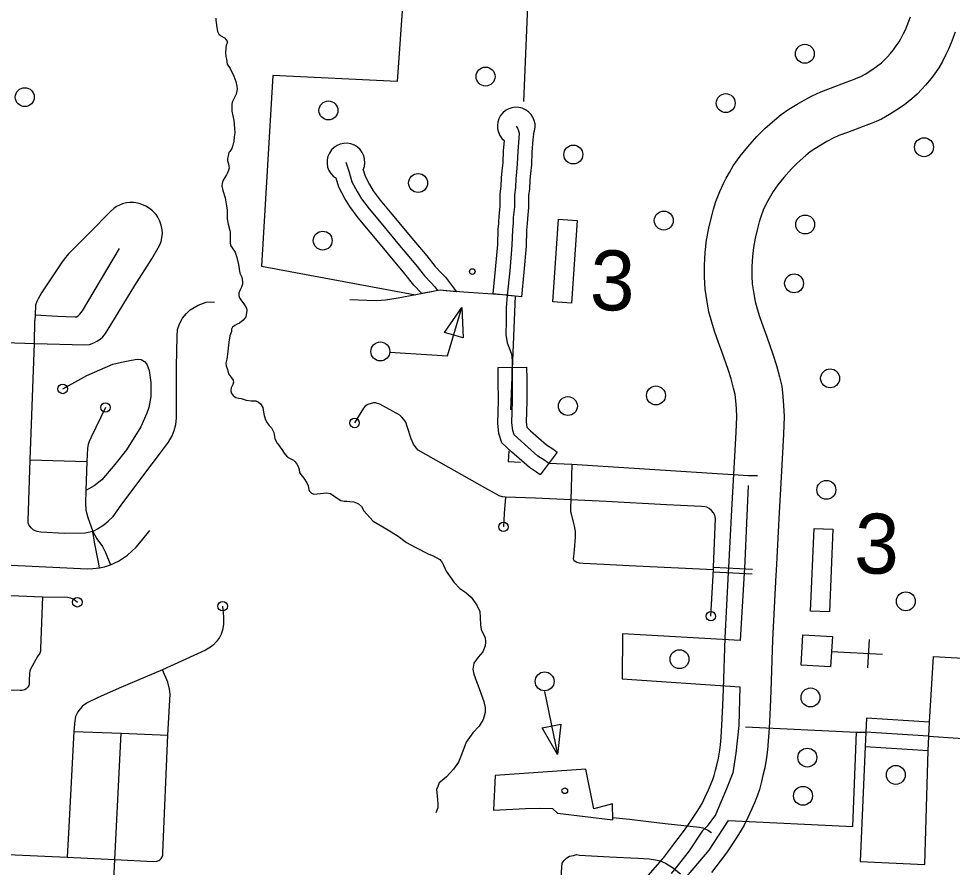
# Model space of a CAD drawing. Extents: x 653372 to 905732, y 627442 to 787275.
# Drawn here: x 671338 to 676272, y 753633 to 758117 of the extents above; entities that cross this region are included whole.
import ezdxf

# ---------------------------------------------------------------- set-up
doc = ezdxf.new("R2010")
doc.units = 0
for name, color, linetype in [('10', 7, 'Continuous'), ('31', 7, 'Continuous'), ('33', 7, 'Continuous'), ('34', 7, 'Continuous'), ('35', 7, 'Continuous'), ('5', 7, 'Continuous'), ('56', 7, 'Continuous'), ('57', 7, 'Continuous'), ('6', 7, 'Continuous')]:
    doc.layers.add(name, color=color, linetype=linetype)

msp = doc.modelspace()

# ---------------------------------------------------------------- linework, layer by layer
at = {"layer": '10'}
for points in [[(674976.3, 756621.1), (674964.7, 756688.7), (674961.6, 756752.6), (674962.4, 756815.5), (674966, 756881.7), (674973.3, 756946.2), (674985.7, 757009.6), (674999.1, 757068.1), (675009.8, 757109.9), (675022.3, 757151.7), (675042.5, 757204.3), (675061.9, 757245.4), (675076.8, 757274.8), (675094.1, 757304.6), (675114.4, 757339.7), (675150.9, 757390.5), (675190.5, 757439.6), (675239.2, 757494.6), (675281.2, 757536.8), (675334.4, 757582.9), (675367.1, 757611), (675407.5, 757639.5), (675451.5, 757666), (675488.5, 757686.5), (675530.8, 757709.8), (675576.2, 757729.9), (675627.9, 757750.1), (675711.1, 757781), (675749.8, 757796.3), (675774.4, 757806.2), (675787.8, 757811.7), (675810.8, 757824.8), (675840.4, 757843.5), (675870.3, 757864.1), (675896.5, 757884.5), (675911.3, 757897.9), (675928.5, 757916), (675942.6, 757931.2), (675960.5, 757952.7), (675975.6, 757974.3), (675990.8, 757994.8), (675999.7, 758010.4), (676014.4, 758039), (676023.8, 758058.2), (676033.4, 758081.6), (676050.9, 758127.4)], [(676287.1, 758045.1), (676265.8, 757989.2), (676251.9, 757955.6), (676238, 757927.1), (676219.6, 757891.3), (676200.5, 757857.9), (676178.4, 757828.1), (676159.3, 757800.8), (676130.3, 757766), (676110.6, 757744.8), (676086, 757718.9), (676057.6, 757693.1), (676018.3, 757662.5), (675978.2, 757634.8), (675939.5, 757610.4), (675897.5, 757586.5), (675868.4, 757574.6), (675842.5, 757564.1), (675800.7, 757547.6), (675716.9, 757516.5), (675672.4, 757499.1), (675642, 757485.6), (675609.2, 757467.5), (675576.5, 757449.5), (675544.3, 757430), (675521, 757413.6), (675497.8, 757393.6), (675451.8, 757353.8), (675421.5, 757323.4), (675381.5, 757278.2), (675349.9, 757238.9), (675324.6, 757203.9), (675310.4, 757179.2), (675296.5, 757155.4), (675286.6, 757135.7), (675272.6, 757106.1), (675259.1, 757070.9), (675250.8, 757043.1), (675242.1, 757009.2), (675230.3, 756957.8), (675220.6, 756908), (675215.2, 756860.7), (675212.3, 756807.2), (675211.7, 756757.1), (675213.7, 756716), (675222.7, 756663.4)], [(675222.8, 756663.1), (675229.6, 756622.3), (675240.6, 756583.5), (675252.7, 756544.2), (675272.3, 756488.6), (675288.9, 756441.7), (675323.3, 756345), (675343.2, 756284), (675358.2, 756224.8), (675369.9, 756175.9), (675376.7, 756121.6), (675380, 756072.4), (675383.1, 756014.3), (675379.3, 755921), (675366.5, 755693.9), (675355.8, 755508.4), (675340.9, 755202.2), (675339.2, 755175.9), (675321.9, 754835.4), (675312.5, 754565.9), (675309, 754477.9), (675304, 754368.3), (675298.9, 754300.3), (675295.2, 754253.8), (675289.9, 754213.4), (675280.1, 754159.3), (675270.8, 754118.9), (675263.7, 754085.7), (675252.1, 754044.6), (675240, 754009.4), (675225.7, 753973.9), (675212.8, 753942.2), (675191.2, 753896.3), (675171.3, 753856.1), (675150.4, 753820.1), (675129.8, 753786.4), (675102.1, 753746.3), (675078.1, 753710.1), (675044.9, 753665.4), (674999.1, 753605.1)], [(674666.9, 753592.2), (674725.5, 753661.1), (674742.9, 753681.8), (674746.7, 753685.7), (674799.8, 753756), (674845, 753815.5), (674873.4, 753853.8), (674895.1, 753886.5), (674920.2, 753922.8), (674935.6, 753948), (674950.9, 753974.3), (674966.1, 754005), (674983.8, 754042.7), (674994, 754067.8), (675005.6, 754096.6), (675013.3, 754119), (675020.9, 754145.9), (675026.7, 754173.2), (675035.2, 754209.7), (675042.8, 754251.9), (675046.5, 754279.9), (675049.6, 754319.6), (675054.4, 754383.5), (675059.3, 754488.6), (675062.7, 754575.2), (675072.1, 754846.1), (675089.6, 755190.5), (675091.3, 755216.5), (675106.2, 755521.7), (675116.9, 755708.2), (675129.6, 755933.1), (675132.8, 756012.6), (675130.4, 756057.5), (675127.8, 756097.7), (675123.6, 756131.1), (675115.4, 756165), (675102.9, 756214.5), (675086.7, 756264.3), (675053.2, 756358.2), (675036.6, 756405.3), (675015.2, 756465.8), (675000.8, 756512.9), (674985.4, 756567.4), (674976.3, 756621.4)]]:
    msp.add_lwpolyline(points, dxfattribs=at)
at = {"layer": '31'}
for p, q in [((673291.9, 756872.5), (673291.9, 756872.5)), ((674022.4, 756208.1), (674022.4, 756208.1)), ((674183.8, 755827.2), (674093.8, 755707.2))]:
    msp.add_line(p, q, dxfattribs=at)
for points in [[(673967.4, 757549), (673974, 757538.7), (673979.9, 757523.7), (673983.3, 757511.9), (673980.9, 757485.4), (673975.7, 757416.6), (673972.6, 757349.8), (673968.1, 757306.2), (673964.9, 757270.7), (673962.5, 757224.6), (673957.6, 757187), (673957.3, 757123.3), (673951.9, 757067.2), (673950.5, 757039.1), (673947.3, 757002), (673944.3, 756919.7), (673932.8, 756785.1), (673920.2, 756655.4)], [(674058.2, 757507), (674055.7, 757479.2), (674050.5, 757412), (674047.4, 757344.2), (674042.7, 757299), (674039.7, 757265.3), (674037.2, 757217.8), (674032.6, 757182), (674032.3, 757119.5), (674026.7, 757061.8), (674025.4, 757034), (674024.1, 757019.5)], [(673874.7, 757032.6), (673875.7, 757044.2), (673877.1, 757072.6), (673882.3, 757127.1), (673882.6, 757192), (673887.7, 757231.4), (673890.1, 757276), (673893.4, 757313.4), (673897.8, 757355.3), (673900.8, 757421.2), (673904.6, 757471.2)], [(673067.2, 757359.1), (673083.7, 757306.4), (673099.2, 757255.8), (673126.7, 757203.8), (673149.6, 757166), (673190.1, 757111.6), (673253.1, 757036.4), (673342.2, 756929.4), (673436.1, 756816.2), (673483.1, 756757.6), (673517.5, 756721.6), (673535.7, 756702.5), (673551.8, 756681.5)], [(673158.5, 757318.3), (673168.8, 757284.6), (673192, 757240.8), (673211.9, 757207.9), (673249, 757158.1), (673310.7, 757084.5), (673399.8, 756977.3), (673407.4, 756968.3)], [(673291.9, 756872.5), (673284.5, 756881.5), (673195.5, 756988.4), (673131.3, 757065.1), (673087.4, 757124), (673061.4, 757166.8), (673029.6, 757227), (673015.3, 757273.6)], [(673994.9, 756648.1), (673845.6, 756662.6), (673858.1, 756791.9), (673869.4, 756924.2), (673872.4, 757006.6), (673874.7, 757032.6)], [(674024.1, 757019.5), (674022.2, 756997.4), (674019.2, 756915.1), (674007.5, 756778.3), (673994.9, 756648.1)], [(673407.4, 756968.3), (673494.2, 756863.6), (673539.6, 756807.1), (673571.8, 756773.3), (673592.8, 756751.3), (673651.5, 756674.6), (673565.8, 756681.8), (673468.3, 756664.5)], [(673468.3, 756664.5), (673426.6, 756708.2), (673378, 756768.8), (673291.9, 756872.5)], [(673872.4, 756207.2), (673872.4, 756212), (673871.6, 756273.3), (674021.6, 756275.3)], [(674138.8, 755767.2), (674117.5, 755783.1), (674082.2, 755806.4), (673993, 755884), (673956.6, 755918.4), (673948.9, 755940.8), (673944.6, 755982.5), (673948.1, 756097.6), (673947.4, 756212.7), (673946.6, 756274.3)], [(674021.6, 756275.3), (674022.4, 756213.5), (674022.4, 756208.1)], [(674093.8, 755707.2), (674074.4, 755721.8), (674036.8, 755746.5), (673942.6, 755828.4), (673891.6, 755876.6), (673875.2, 755924.7), (673869.5, 755979.8), (673873.1, 756098.5), (673872.4, 756207.2)], [(674022.4, 756208.1), (674023.1, 756096.7), (674019.8, 755985.3), (674022.4, 755959.4), (674043.4, 755939.6), (674127.6, 755866.3), (674160.7, 755844.5), (674183.8, 755827.2)], [(676150.9, 754400.8), (675818.5, 754421.4), (675811.9, 754271.5)], [(676150.9, 754400.8), (675818.5, 754421.4), (675811.9, 754271.5)], [(675811.9, 754271.5), (676144, 754251), (676150.9, 754400.8)], [(676146.3, 754326), (675815.2, 754346.4)]]:
    msp.add_lwpolyline(points, dxfattribs=at)
for centre, start, end in [((673967.4, 757549), 335.1349, 231.0844), ((673067.2, 757359.1), 335.9073, 238.725)]:
    msp.add_arc(centre, 100, start, end, dxfattribs=at)
at = {"layer": '33'}
for points in [[(671267.5, 756405.4), (671421.3, 756401.1), (671688.5, 756393.3), (671711.7, 756396), (671734.7, 756404.2), (671754.2, 756414.5), (671769.3, 756424.4), (671783.5, 756436.8), (671797.5, 756453.2), (671825.1, 756499.2), (671951.2, 756707.2), (672041.8, 756848.1), (672075.1, 756905.8), (672083.5, 756921.8), (672090.4, 756940.4), (672094.4, 756959), (672097.6, 756981.6), (672096.7, 757000.7), (672090.5, 757026.5), (672083.3, 757047.5), (672074, 757068.5), (672065.1, 757082.6), (672045.9, 757101.4), (672030, 757113.7), (672009.7, 757126.7), (671989.2, 757135.7), (671974.1, 757141.1), (671957.4, 757144.5), (671944.1, 757145.4), (671925.9, 757146), (671908.1, 757144), (671886.7, 757138.3), (671871.2, 757132.3), (671854.7, 757123.9), (671840.5, 757113.5), (671822.8, 757097.7), (671715.4, 756988.9), (671651, 756923.2), (671602.2, 756873.9), (671579.2, 756846.9), (671563.8, 756827.6), (671526, 756768.3), (671458.9, 756668.7), (671440.7, 756637.1), (671433.3, 756622.6), (671427.8, 756604), (671425.4, 756553), (671424, 756523.1)], [(673920.2, 756655.4), (673715.6, 756670.1), (673594.4, 756678.5), (673565.8, 756681.8), (673551.8, 756681.5), (673544.5, 756680), (673528.1, 756675.8), (673436.4, 756658.5), (673343, 756639.9), (673276.5, 756629), (673253.1, 756627.3), (673227.9, 756626.2), (673177.6, 756627.2), (673088.2, 756631.8)], [(673920.2, 756655.4), (673914.3, 756589.6), (673913.6, 756518.9), (673912.9, 756448.2), (673919.9, 756405), (673930.2, 756378.3), (673943, 756344.6), (673946.2, 756311.3), (673946.6, 756274.3)], [(671729.8, 755408.2), (671755.4, 755421.3), (671788.1, 755443), (671811.4, 755461.6), (671837.3, 755486.4), (671879.5, 755545.9), (671998.8, 755707.1), (672087.7, 755823.1), (672129.8, 755879.1), (672148.6, 755913.5), (672160.3, 755941.8), (672168.2, 755973.7), (672171.6, 756005.6), (672172.6, 756107.5), (672172.8, 756279.2), (672175.6, 756438.1), (672177.2, 756474.1), (672187.5, 756503.9), (672204.2, 756535.5), (672224.7, 756559.5), (672244.5, 756578.7), (672286, 756604.1), (672328.4, 756619.1), (672352.6, 756621.3), (672373.3, 756619.2)], [(671729.8, 755408.2), (671689.1, 755398.1), (671580, 755397.4), (671455.9, 755404.1), (671435.7, 755407.2), (671424.5, 755411), (671414.3, 755416.7), (671403.3, 755426.4), (671396.6, 755436), (671392.4, 755443.5), (671388.7, 755452.1), (671387.7, 755463.9), (671399.4, 755785.9), (671421.3, 756401.1), (671424, 756523.1)], [(671796.4, 756062.7), (671720.6, 755906), (671711.1, 755883.6), (671705.1, 755866.5), (671701.1, 755847.9), (671698.6, 755777), (671692.6, 755623.5), (671691.9, 755556.9), (671692.8, 755520.8), (671704.4, 755481), (671729.8, 755408.2)], [(675009.6, 755207), (675010.2, 755219.8), (675019.5, 755476.3), (675016, 755493.4), (675009.1, 755506.6), (674999.8, 755517.6), (674987.5, 755528.7), (674974.3, 755536), (674963, 755538.6), (674945.5, 755540.2), (674760.7, 755549.2), (674441.6, 755565.6), (674255.8, 755574), (674069.8, 755583.5), (673910.1, 755588.3), (673894.8, 755590.5), (673876.3, 755596.7), (673851.8, 755609.9), (673801.7, 755639.1), (673448.7, 755836.7), (673437.8, 755849.4), (673424.2, 755869.1), (673412.6, 755897.2), (673392.3, 755957.3), (673383, 755985.3), (673372.6, 755999.8), (673363.4, 756011.9), (673352.4, 756022.4), (673246.7, 756079.9), (673224.3, 756087.4), (673212.4, 756087.2), (673182.2, 756078.5), (673169.4, 756070.4), (673159.5, 756059.9), (673113, 755980.9)], [(671399.4, 755785.9), (671698.6, 755777)], [(675241.7, 755701.1), (675194.8, 755702.3), (674590.6, 755741.2), (674260.3, 755761.5), (674138.8, 755767.2)], [(674260.3, 755761.5), (674255.8, 755574), (674253.9, 755534), (674254.4, 755513.6), (674256.8, 755501), (674270.6, 755450), (674275.6, 755429.5), (674277.8, 755405.6), (674278.1, 755377.9), (674273.8, 755310.6), (674269.3, 755275), (674268.4, 755263.7), (674272.1, 755256.3), (674278.2, 755251), (674287.7, 755245.6), (674299.4, 755241.9), (674320.4, 755240.7), (674430.6, 755234.5), (674564.6, 755227.7), (675009.6, 755206.9)], [(673910.1, 755588.3), (673903.6, 755503), (673899.8, 755431.7)], [(671224.2, 755233.5), (671701.3, 755210.2), (671730.3, 755211.8), (671764.4, 755216.4), (671791.3, 755221.6), (671822.5, 755231.3), (671865.2, 755250.7), (671913.6, 755281.8), (671959.3, 755324.9), (671987.9, 755357.6), (672031.1, 755413.5)], [(671764.4, 755216.4), (671760.5, 755244.9), (671753.2, 755281.2), (671738, 755350.3), (671729.8, 755408.2), (671751.4, 755369.6), (671780.7, 755327.8), (671797, 755295.7), (671822.5, 755231.3)], [(674995.9, 754959.9), (675009.6, 755207)], [(675009, 755193.7), (675214.4, 755183.2)], [(675010.2, 755219.8), (675216.1, 755209.3)], [(671463.7, 755062.5), (671454.1, 754789.3), (671453.7, 754775.7), (671449.4, 754764.6), (671438.4, 754746.6), (671400.9, 754680.5), (671397, 754670.3), (671394.6, 754658.7), (671393.4, 754619.2), (671393.1, 754602.2), (671391.3, 754594.6), (671386.2, 754585.2), (671378.4, 754577), (671370.6, 754571.7), (671363.4, 754569.1), (671354.1, 754567.4), (671346.1, 754566.8), (671192.5, 754573)], [(671211.8, 755072), (671463.7, 755062.5), (671596.1, 755059.7), (671612.4, 755057.2), (671623.9, 755052.5), (671636, 755044.9), (671648.1, 755033.4)], [(672416, 755012.8), (672420.8, 754956.6), (672419.6, 754915.7), (672415.5, 754886.2), (672408.4, 754864.9), (672398.7, 754846.8), (672383, 754825.8), (672366.8, 754809), (672352.4, 754796), (672326.1, 754781.1), (672097.2, 754675.9), (671868.7, 754579.7), (671755.1, 754528.7), (671704.3, 754503.3), (671683.5, 754491), (671673.5, 754482.1), (671662.9, 754471.1), (671650.1, 754454.6), (671637.5, 754429.7), (671634.1, 754409.3), (671629.8, 754351.2), (671603.3, 753846.7), (671594, 753687.2)], [(671845.8, 753673.7), (672049, 753663.8), (672067.9, 753665.4), (672078.7, 753668.3), (672084.8, 753673), (672091.5, 753680.3), (672096.6, 753689.3), (672099.5, 753696.8), (672100.5, 753711.3), (672126.8, 754331.4), (672138.6, 754548), (672135.6, 754575), (672125.4, 754612), (672097.2, 754675.9)], [(671629.8, 754351.2), (671879.9, 754341.5), (672126.8, 754331.4)], [(671832.9, 753385.8), (671845.8, 753673.7), (671879.9, 754341.5)], [(675179.2, 754375.9), (675765.3, 754346.7), (675815.2, 754346.4)], [(676146.3, 754326), (676302.1, 754314.7), (676400.2, 754308.6), (676470.9, 754301.1)], [(674478.1, 753896.6), (674566.6, 753887.2), (674652.5, 753877.1), (674754, 753865), (674935.6, 753845.3), (674953.1, 753842), (674962.9, 753838.3), (674979.2, 753829.3), (674998.6, 753816.4)], [(671161.8, 753705.6), (671594, 753687.2), (671845.8, 753673.7)], [(674183.2, 753167.3), (674180.7, 753197.8), (674184.6, 753261.1), (674195, 753428.1), (674207.4, 753636.2), (674210.6, 753655), (674220.5, 753668.9), (674235.1, 753682.6), (674249.5, 753692.3), (674269.2, 753696.4), (674285.5, 753700), (674300.9, 753697.5), (674460.5, 753688.7), (674609.4, 753682.2), (674669.6, 753677.7), (674702.6, 753673.3), (674727.3, 753666.5), (674756.6, 753654.8), (674793.1, 753632.8), (674835.7, 753598)]]:
    msp.add_lwpolyline(points, dxfattribs=at)
for centre in [(671796.4, 756062.7), (673113, 755980.9), (673899.8, 755431.7), (671648.1, 755033.4), (672416, 755012.8), (674995.9, 754959.9)]:
    msp.add_circle(centre, 25, dxfattribs=at)
at = {"layer": '34'}
for points in [[(671425.4, 756553), (671543, 756546.1), (671634, 756541.2), (671644.4, 756541.6), (671652.8, 756547.3), (671661.1, 756555.2), (671675.1, 756574), (671871.7, 756903.3)], [(671570.6, 756160.6), (671698, 756231.8), (671835, 756290.9), (671880.7, 756302.4), (671933.4, 756313.6), (671964.1, 756318.6), (671985.7, 756316), (672003.2, 756306.6), (672015.6, 756292.4), (672027.4, 756258.5), (672036.4, 756195), (672037.1, 756121), (672025.5, 756063.1), (672015.7, 756032.8), (671983.9, 755960.7), (671908.2, 755838.2), (671845.7, 755762.1), (671777.2, 755681.2), (671737.8, 755648.8), (671692.6, 755623.5)]]:
    msp.add_lwpolyline(points, dxfattribs=at)
msp.add_circle((671570.6, 756160.6), 25, dxfattribs=at)
at = {"layer": '35'}
for points in [[(672379.5, 758119.3), (672379.5, 758107), (672382.1, 758096.5), (672385.5, 758070.8), (672388.9, 758049), (672395.3, 758036.1), (672402.9, 758029.9), (672406.9, 758025.7), (672424.9, 758016.2), (672433.9, 758005.5), (672438.9, 757997.9), (672439.4, 757987.8), (672434.6, 757977.8), (672433.3, 757961.8), (672430.8, 757938), (672432.8, 757918.1), (672435.7, 757902.6), (672440.5, 757877), (672455.1, 757853.8), (672474.8, 757813.6), (672486.3, 757784.5), (672490, 757760.9), (672492.6, 757746.6), (672491.1, 757735.3), (672487.6, 757717.5), (672474.9, 757694), (672466.6, 757675.5), (672464.7, 757662.9), (672465, 757649.8), (672465.1, 757628.7), (672474.5, 757579.2), (672479.2, 757537.9), (672481.1, 757513.2), (672476.3, 757492.1), (672475, 757470.5), (672469.8, 757449), (672464.1, 757432), (672453.2, 757415.9), (672449.3, 757410.5), (672444.2, 757392), (672441.9, 757377.9), (672441.6, 757366.7), (672446.7, 757349.7), (672449, 757338.5), (672449.7, 757327.2), (672446.5, 757317.3), (672442.3, 757303.2), (672436.4, 757291.7), (672418.7, 757263.5), (672413.4, 757247.2), (672411.9, 757233.8), (672417.5, 757209.7), (672428.6, 757169.8), (672435.9, 757127.4), (672440.1, 757104.5), (672439.9, 757084.7), (672439.5, 757059.6), (672445, 757032.1), (672454, 756997.1), (672455, 756991.7)], [(672455, 756991.7), (672455.8, 756935.1), (672457.4, 756919.5), (672466.4, 756906.7), (672481.8, 756883.9), (672491.4, 756856.1), (672499.1, 756817.4), (672506.6, 756773), (672516.8, 756751.5), (672520.2, 756726.9), (672520.4, 756713.9), (672515.7, 756698.5), (672505.9, 756680.6), (672501.3, 756667.2), (672500.9, 756655.3), (672504.2, 756641.7), (672516.2, 756626.2), (672528.2, 756611.3), (672534.6, 756600.2), (672541.5, 756587.5), (672543.2, 756575.5), (672540.4, 756551.5), (672538, 756540.1), (672533.7, 756534), (672525.1, 756524.4), (672504.3, 756507.9), (672492.7, 756503.6), (672479.6, 756496.7), (672468.4, 756487.7), (672461.8, 756475.9), (672462, 756464.5), (672454, 756441.8), (672448.3, 756407.2), (672442.3, 756345), (672438.3, 756317.6), (672432.5, 756297), (672434.7, 756283.4), (672440.8, 756262.9), (672447.5, 756240.9), (672461.9, 756220.2), (672470.9, 756208), (672472.6, 756197), (672470.2, 756184.1), (672460.3, 756166.2), (672458.8, 756152.7), (672461, 756139.7), (672471.5, 756125.9), (672486.3, 756116.1), (672501.8, 756111.4), (672514.2, 756111.1)], [(672514.2, 756111.1), (672540.8, 756100.7), (672566.7, 756098.3), (672592.1, 756097.5), (672604.9, 756091.4), (672616, 756081.8), (672628.5, 756062.7), (672631.4, 756038.7), (672635.5, 756019.9), (672642.1, 755997.8), (672650.4, 755981.5), (672662, 755967.1), (672674.6, 755955.8), (672686.3, 755930), (672692.1, 755898.3), (672702.9, 755876.2), (672707.9, 755870.3), (672729.3, 755840.5), (672740.7, 755821.5), (672756.8, 755802.3), (672773.1, 755792.5), (672790.5, 755784.1), (672797.6, 755777.2), (672806.1, 755766), (672815, 755751.2), (672820.2, 755734.9), (672822.8, 755718.7), (672828.8, 755708.7), (672844.5, 755688.7), (672861.4, 755665.3), (672868.2, 755648.5), (672871.3, 755630.2), (672875.1, 755620.2), (672881.2, 755614.3), (672884.7, 755610.6), (672897.5, 755604.5), (672914.8, 755607.1), (672967.2, 755612), (672986.5, 755608.6), (673003.6, 755595.2), (673021.5, 755584.3), (673040.2, 755571.4), (673058.5, 755567.9), (673072.5, 755567), (673088.6, 755565.5), (673108.3, 755564.4), (673118.4, 755560.7), (673133.4, 755553.7), (673150.1, 755539.2), (673162.2, 755517.3), (673176.2, 755500.2), (673212, 755462.8)], [(673212, 755462.8), (673282.9, 755419.6), (673343.1, 755383), (673388.1, 755348.7), (673433.1, 755325), (673506, 755288.2), (673528.8, 755278.4), (673563, 755258.7), (673571.1, 755250.7), (673576.1, 755243.2), (673583.5, 755230), (673597.6, 755197.9), (673640, 755138.9), (673669.1, 755106.9), (673701.7, 755085.1), (673729.6, 755059.8)], [(673729.6, 755059.8), (673758.2, 755017.8), (673775.6, 754985.1), (673776.9, 754952.9), (673778.8, 754914.5), (673782.6, 754889.1), (673791.9, 754867.4), (673802.8, 754847.2), (673804.4, 754822.6), (673802.3, 754802.8), (673790.6, 754772.5), (673765.3, 754743.4), (673743.6, 754711.8), (673738.1, 754679.8), (673743.4, 754653.6), (673756.8, 754615.7), (673771.8, 754578.5), (673796.5, 754509.6), (673803.2, 754476.4), (673803.9, 754450.4), (673792.1, 754413.5), (673771.2, 754379.6), (673737.2, 754343.1), (673702.8, 754294.4), (673680.2, 754233), (673661.3, 754188.8), (673635.7, 754151.2), (673598.5, 754111.8), (673575, 754092.5), (673560.8, 754080), (673552.6, 754061), (673545.9, 754043.6), (673549.5, 754010.6), (673553.6, 753969.1), (673553, 753947.7), (673543, 753921.2)]]:
    msp.add_lwpolyline(points, dxfattribs=at)
at = {"layer": '5'}
msp.add_lwpolyline([(674064.1, 759067.3), (674005.6, 757679.8)], dxfattribs=at)
at = {"layer": '56'}
for p, q in [((673588.3, 756459.4), (673680.5, 756591.7)), ((673680.5, 756591.7), (673686.1, 756430.5)), ((673686.1, 756430.5), (673588.3, 756459.4)), ((674103.8, 754369.4), (674203.7, 754390)), ((674203.7, 754390), (674184.7, 754229.8)), ((674184.7, 754229.8), (674103.8, 754369.4))]:
    msp.add_line(p, q, dxfattribs=at)
for points in [[(674190, 757057.9), (674289.8, 757051.1), (674259.7, 756614.6), (674160, 756621.5)], [(675541.1, 755424.1), (675641, 755419.7), (675621.7, 754982.6), (675521.8, 754987)]]:
    msp.add_lwpolyline(points, close=True, dxfattribs=at)
for points in [[(673300.1, 756355.8), (673604.7, 756334.9), (673680.5, 756591.7)], [(674116.1, 754562), (674184.7, 754229.8)]]:
    msp.add_lwpolyline(points, dxfattribs=at)
for centre, radius in [((675492.3, 757931.7), 50), ((673805.1, 757811.4), 50), ((671370.1, 757702.6), 50), ((675074.2, 757671), 50), ((672974.7, 757632.3), 50), ((674268.9, 757399.4), 50), ((676122, 757437.9), 50), ((673448.7, 757248.9), 50), ((674746.9, 757050.5), 50), ((675494, 757029.6), 50), ((672944.7, 756944.5), 50), ((673735.2, 756781), 15), ((675435.3, 756718.6), 50), ((673249.1, 756358.9), 50), ((675625.6, 756216.6), 50), ((674705.6, 756126.5), 50), ((674240.1, 756070.3), 50), ((675606, 755627.7), 50), ((676025.9, 755038.7), 50), ((674829.9, 754732.8), 50), ((674117.3, 754615.6), 50), ((675522, 754530.6), 50), ((675505.5, 754212.8), 50), ((675973, 754121.4), 50), ((674223.9, 754037.6), 15), ((675482.5, 754010.9), 50)]:
    msp.add_circle(centre, radius, dxfattribs=at)
at = {"layer": '57'}
for p, q in [((675831.5, 754836.1), (675823, 754686.3)), ((675902.1, 754756.9), (675633.3, 754772.2))]:
    msp.add_line(p, q, dxfattribs=at)
msp.add_lwpolyline([(675482.1, 754862.1), (675637.9, 754853.3), (675628.7, 754691.7), (675473, 754700.5)], close=True, dxfattribs=at)
at = {"layer": '6'}
for points in [[(673437.4, 759410.1), (673430.8, 759104.5), (673338.7, 757785.1), (672680.7, 757816.1), (672621.9, 756809), (673435.5, 756658.3)], [(673920.2, 756655.4), (673962.4, 756653.5), (673937, 756051.2)], [(673927.8, 755833.1), (673925.4, 755776.7), (673990.6, 755773.7)], [(675192.6, 755650.7), (675173.4, 755211.7), (675171.8, 755188.5), (675150.9, 754831)], [(675150.9, 754831), (674529.5, 754866.6), (674527.5, 754629.7), (675147.9, 754587.4), (675143.4, 754383.2), (675128.1, 754236.3), (675111.5, 754133.2), (675078.2, 754048.1), (675048.9, 753977.9), (675019.7, 753910.1), (674975.4, 753850.7), (674949.3, 753824.5), (674881.8, 753719.5), (674817.3, 753639.1), (674786, 753600.1)], [(676150.9, 754400.8), (676172, 754747.8), (676483.9, 754729.7)], [(674818.2, 753524.3), (674987.2, 753723.2), (675088.1, 753880.3), (675745.5, 753849.5), (675765.3, 754346.7)], [(675811.9, 754271.5), (675785, 753664.4), (676127.1, 753647.4), (676144, 754251)]]:
    msp.add_lwpolyline(points, dxfattribs=at)
msp.add_lwpolyline([(674159.4, 753943.9), (674184.7, 753919.6), (674478.3, 753884.7), (674476.6, 753967.9), (674376.6, 753942), (674335.8, 754151.3), (673855.5, 754118.8), (673847.8, 753935.1), (674016.3, 753943.3), (674096.5, 753945.3)], close=True, dxfattribs=at)

# ---------------------------------------------------------------- texts
at = {"layer": '56'}
for p in [(674353.6, 756579.6), (675750.4, 755188.5)]:
    msp.add_text('3', height=316.8, rotation=358.28, dxfattribs=at).set_placement(p)

doc.saveas('drawing.dxf')
